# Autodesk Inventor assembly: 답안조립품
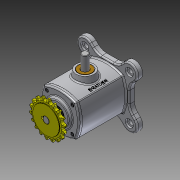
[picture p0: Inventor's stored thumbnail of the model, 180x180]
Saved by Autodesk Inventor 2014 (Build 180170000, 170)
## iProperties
Created: 2016-05
Part Number: 답안조립품
Document SubType Name: Assembly
Designer: G.C.Oh
Author: G.C.Oh
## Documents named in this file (11)
- C:\Users\Administrator\Desktop\460507V1019\답안조립품.iam
- C:\Users\Administrator\Desktop\460507V1019\1-본체.ipt
- C:\Users\Administrator\Desktop\460507V1019\M4x0.7x12.ipt
- C:\Users\Administrator\Desktop\460507V1019\베어링-6203.ipt
- C:\Users\Administrator\Desktop\460507V1019\부시.ipt
- C:\Users\Administrator\Desktop\460507V1019\스프로킷.ipt
- C:\Users\Administrator\Desktop\460507V1019\슬라이더.ipt
- C:\Users\Administrator\Desktop\460507V1019\오일실.ipt
- C:\Users\Administrator\Desktop\460507V1019\커버.ipt
- C:\Users\Administrator\Desktop\460507V1019\키5x5.ipt
- C:\Users\Administrator\Desktop\460507V1019\편심축.ipt
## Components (9 placed, 2 different names)
1. 1-본체:1
2. M4x0.7x12:1
3. M4x0.7x12:6
4. M4x0.7x12:7
5. M4x0.7x12:8
6. M4x0.7x12:2
7. M4x0.7x12:9
8. M4x0.7x12:10
9. M4x0.7x12:11
